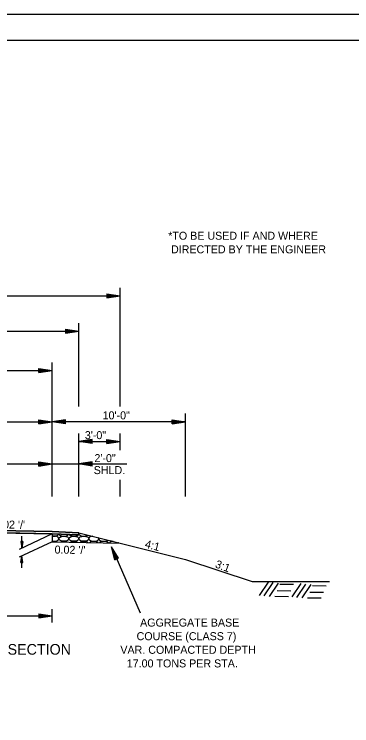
# Model space of a CAD drawing. Extents: x 1371763 to 1372860, y 385599 to 385872.
# Drawn here: x 1372776.6 to 1372801.9, y 385651.9 to 385705.3 of the extents above; entities that cross this region are included whole.
import ezdxf

# ---------------------------------------------------------------- set-up
doc = ezdxf.new("R2010")
doc.units = 0
for name, color, linetype in [('R_Border', 7, 'Continuous'), ('R_Draft', 7, 'Continuous'), ('R_Fin Surface', 7, 'Continuous'), ('R_No Plot', 7, 'Continuous')]:
    doc.layers.add(name, color=color, linetype=linetype)

msp = doc.modelspace()

# ---------------------------------------------------------------- linework, layer by layer
at = {"layer": 'R_Border'}
msp.add_line((1372699.208, 385703.307), (1372857.298, 385703.307), dxfattribs=at)
at = {"layer": 'R_Draft'}
for p, q in [((1372784.547, 385675.852), (1372784.547, 385684.754)), ((1372752.376, 385684.154), (1372784.547, 385684.154)), ((1372783.547, 385684.304), (1372784.547, 385684.154)), ((1372783.547, 385684.304), (1372783.547, 385684.004)), ((1372783.547, 385684.279), (1372784.38, 385684.154)), ((1372783.547, 385684.254), (1372784.208, 385684.154)), ((1372783.547, 385684.229), (1372784.042, 385684.154)), ((1372783.547, 385684.203), (1372783.872, 385684.154)), ((1372783.547, 385684.178), (1372783.705, 385684.154)), ((1372783.547, 385684.004), (1372784.547, 385684.154)), ((1372783.547, 385684.105), (1372783.872, 385684.154)), ((1372783.547, 385684.055), (1372784.208, 385684.154)), ((1372783.547, 385684.029), (1372784.38, 385684.154)), ((1372783.547, 385684.08), (1372784.042, 385684.154)), ((1372783.547, 385684.131), (1372783.705, 385684.154)), ((1372781.46, 385675.852), (1372781.46, 385682.102)), ((1372755.463, 385681.502), (1372781.46, 385681.502)), ((1372780.46, 385681.652), (1372781.46, 385681.502)), ((1372780.46, 385681.652), (1372780.46, 385681.352)), ((1372780.46, 385681.627), (1372781.293, 385681.502)), ((1372780.46, 385681.602), (1372781.121, 385681.502)), ((1372780.46, 385681.577), (1372780.955, 385681.502)), ((1372780.46, 385681.551), (1372780.785, 385681.502)), ((1372780.46, 385681.526), (1372780.618, 385681.502)), ((1372780.46, 385681.352), (1372781.46, 385681.502)), ((1372780.46, 385681.453), (1372780.785, 385681.502)), ((1372780.46, 385681.403), (1372781.121, 385681.502)), ((1372780.46, 385681.377), (1372781.293, 385681.502)), ((1372780.46, 385681.428), (1372780.955, 385681.502)), ((1372780.46, 385681.479), (1372780.618, 385681.502)), ((1372778.462, 385678.697), (1372779.462, 385678.547)), ((1372778.462, 385678.397), (1372778.462, 385678.697)), ((1372778.462, 385678.672), (1372779.295, 385678.547)), ((1372779.462, 385669.102), (1372779.462, 385679.147)), ((1372757.462, 385678.546), (1372779.462, 385678.547)), ((1372778.462, 385678.646), (1372779.123, 385678.547)), ((1372778.462, 385678.621), (1372778.956, 385678.547)), ((1372778.462, 385678.596), (1372778.787, 385678.547)), ((1372778.462, 385678.57), (1372778.62, 385678.547)), ((1372778.462, 385678.397), (1372779.462, 385678.547)), ((1372778.462, 385678.498), (1372778.787, 385678.547)), ((1372778.462, 385678.447), (1372779.123, 385678.547)), ((1372778.462, 385678.422), (1372779.295, 385678.547)), ((1372778.462, 385678.472), (1372778.956, 385678.547)), ((1372778.462, 385678.523), (1372778.62, 385678.547)), ((1372789.462, 385669.102), (1372789.462, 385675.327)), ((1372757.462, 385674.702), (1372779.462, 385674.702)), ((1372778.462, 385674.852), (1372779.462, 385674.702)), ((1372778.462, 385674.552), (1372778.462, 385674.852)), ((1372778.462, 385674.827), (1372779.295, 385674.702)), ((1372778.462, 385674.802), (1372779.123, 385674.702)), ((1372778.462, 385674.777), (1372778.956, 385674.702)), ((1372778.462, 385674.751), (1372778.787, 385674.702)), ((1372778.462, 385674.726), (1372778.62, 385674.702)), ((1372778.462, 385674.552), (1372779.462, 385674.702)), ((1372778.462, 385674.654), (1372778.787, 385674.702)), ((1372778.462, 385674.603), (1372779.123, 385674.702)), ((1372778.462, 385674.577), (1372779.295, 385674.702)), ((1372778.462, 385674.628), (1372778.956, 385674.702)), ((1372778.462, 385674.679), (1372778.62, 385674.702)), ((1372780.462, 385674.852), (1372779.462, 385674.702)), ((1372789.462, 385674.702), (1372779.462, 385674.702)), ((1372780.462, 385674.552), (1372779.462, 385674.702)), ((1372780.462, 385674.827), (1372779.629, 385674.702)), ((1372780.462, 385674.577), (1372779.629, 385674.702)), ((1372780.462, 385674.802), (1372779.801, 385674.702)), ((1372780.462, 385674.603), (1372779.801, 385674.702)), ((1372780.462, 385674.777), (1372779.967, 385674.702)), ((1372780.462, 385674.628), (1372779.967, 385674.702)), ((1372780.462, 385674.751), (1372780.137, 385674.702)), ((1372780.462, 385674.654), (1372780.137, 385674.702)), ((1372780.462, 385674.726), (1372780.304, 385674.702)), ((1372780.462, 385674.679), (1372780.304, 385674.702)), ((1372780.462, 385674.552), (1372780.462, 385674.852)), ((1372788.462, 385674.852), (1372789.462, 385674.702)), ((1372788.462, 385674.552), (1372788.462, 385674.852)), ((1372788.462, 385674.827), (1372789.295, 385674.702)), ((1372788.462, 385674.802), (1372789.123, 385674.702)), ((1372788.462, 385674.777), (1372788.956, 385674.702)), ((1372788.462, 385674.751), (1372788.787, 385674.702)), ((1372788.462, 385674.726), (1372788.62, 385674.702)), ((1372788.462, 385674.552), (1372789.462, 385674.702)), ((1372788.462, 385674.654), (1372788.787, 385674.702)), ((1372788.462, 385674.603), (1372789.123, 385674.702)), ((1372788.462, 385674.577), (1372789.295, 385674.702)), ((1372788.462, 385674.628), (1372788.956, 385674.702)), ((1372788.462, 385674.679), (1372788.62, 385674.702)), ((1372781.46, 385669.102), (1372781.46, 385673.818)), ((1372782.46, 385673.368), (1372781.46, 385673.218)), ((1372782.46, 385673.343), (1372781.627, 385673.218)), ((1372782.46, 385673.318), (1372781.799, 385673.218)), ((1372782.46, 385673.068), (1372782.46, 385673.368)), ((1372783.547, 385673.368), (1372784.547, 385673.218)), ((1372783.547, 385673.068), (1372783.547, 385673.368)), ((1372783.547, 385673.343), (1372784.38, 385673.218)), ((1372783.547, 385673.318), (1372784.208, 385673.218)), ((1372784.547, 385672.568), (1372784.547, 385673.818)), ((1372782.46, 385673.068), (1372781.46, 385673.218)), ((1372781.46, 385673.218), (1372784.547, 385673.218)), ((1372782.46, 385673.093), (1372781.627, 385673.218)), ((1372782.46, 385673.119), (1372781.799, 385673.218)), ((1372782.46, 385673.293), (1372781.966, 385673.218)), ((1372782.46, 385673.144), (1372781.966, 385673.218)), ((1372782.46, 385673.267), (1372782.135, 385673.218)), ((1372782.46, 385673.17), (1372782.135, 385673.218)), ((1372782.46, 385673.242), (1372782.302, 385673.218)), ((1372782.46, 385673.195), (1372782.302, 385673.218)), ((1372783.547, 385673.293), (1372784.042, 385673.218)), ((1372783.547, 385673.267), (1372783.872, 385673.218)), ((1372783.547, 385673.242), (1372783.705, 385673.218)), ((1372783.547, 385673.068), (1372784.547, 385673.218)), ((1372783.547, 385673.17), (1372783.872, 385673.218)), ((1372783.547, 385673.119), (1372784.208, 385673.218)), ((1372783.547, 385673.093), (1372784.38, 385673.218)), ((1372783.547, 385673.144), (1372784.042, 385673.218)), ((1372783.547, 385673.195), (1372783.705, 385673.218)), ((1372768.458, 385671.541), (1372785.058, 385671.541)), ((1372778.458, 385671.691), (1372779.458, 385671.541)), ((1372778.458, 385671.391), (1372778.458, 385671.691)), ((1372778.458, 385671.666), (1372779.291, 385671.541)), ((1372778.458, 385671.64), (1372779.119, 385671.541)), ((1372778.458, 385671.615), (1372778.953, 385671.541)), ((1372778.458, 385671.59), (1372778.783, 385671.541)), ((1372778.458, 385671.564), (1372778.616, 385671.541)), ((1372778.458, 385671.391), (1372779.458, 385671.541)), ((1372778.458, 385671.492), (1372778.783, 385671.541)), ((1372778.458, 385671.441), (1372779.119, 385671.541)), ((1372778.458, 385671.416), (1372779.291, 385671.541)), ((1372778.458, 385671.466), (1372778.953, 385671.541)), ((1372778.458, 385671.517), (1372778.616, 385671.541)), ((1372782.46, 385671.691), (1372781.46, 385671.541)), ((1372782.46, 385671.391), (1372781.46, 385671.541)), ((1372782.46, 385671.666), (1372781.627, 385671.541)), ((1372782.46, 385671.416), (1372781.627, 385671.541)), ((1372782.46, 385671.64), (1372781.799, 385671.541)), ((1372782.46, 385671.441), (1372781.799, 385671.541)), ((1372782.46, 385671.615), (1372781.966, 385671.541)), ((1372782.46, 385671.466), (1372781.966, 385671.541)), ((1372782.46, 385671.59), (1372782.135, 385671.541)), ((1372782.46, 385671.492), (1372782.135, 385671.541)), ((1372782.46, 385671.564), (1372782.302, 385671.541)), ((1372782.46, 385671.517), (1372782.302, 385671.541)), ((1372782.46, 385671.391), (1372782.46, 385671.691)), ((1372784.547, 385669.102), (1372784.547, 385670.352)), ((1372768.462, 385666.689), (1372779.462, 385666.469)), ((1372779.462, 385666.469), (1372768.462, 385666.689)), ((1372768.462, 385666.523), (1372779.462, 385666.303)), ((1372779.462, 385666.469), (1372781.46, 385666.389)), ((1372781.46, 385666.389), (1372779.462, 385666.469)), ((1372781.46, 385666.389), (1372789.46, 385664.389)), ((1372781.46, 385666.389), (1372781.46, 385666.223)), ((1372779.462, 385666.303), (1372776.974, 385665.131)), ((1372777.187, 385665.231), (1372777.187, 385666.131)), ((1372779.462, 385666.303), (1372779.462, 385665.719)), ((1372779.462, 385665.719), (1372776.974, 385664.547)), ((1372777.112, 385665.731), (1372777.187, 385665.231)), ((1372777.262, 385665.731), (1372777.112, 385665.731)), ((1372777.124, 385665.731), (1372777.187, 385665.314)), ((1372777.137, 385665.731), (1372777.187, 385665.4)), ((1372777.15, 385665.731), (1372777.187, 385665.484)), ((1372777.162, 385665.731), (1372777.187, 385665.568)), ((1372777.175, 385665.731), (1372777.187, 385665.652)), ((1372777.262, 385665.731), (1372777.187, 385665.231)), ((1372777.211, 385665.731), (1372777.187, 385665.568)), ((1372777.237, 385665.731), (1372777.187, 385665.4)), ((1372777.249, 385665.731), (1372777.187, 385665.314)), ((1372777.224, 385665.731), (1372777.187, 385665.484)), ((1372777.199, 385665.731), (1372777.187, 385665.652)), ((1372779.462, 385665.719), (1372784.547, 385665.618)), ((1372784.163, 385664.362), (1372783.898, 385665.338)), ((1372784.437, 385664.482), (1372783.898, 385665.338)), ((1372783.898, 385665.338), (1372786.069, 385660.393)), ((1372784.186, 385664.372), (1372783.965, 385665.185)), ((1372784.415, 385664.472), (1372783.965, 385665.185)), ((1372784.391, 385664.462), (1372784.034, 385665.027)), ((1372784.209, 385664.382), (1372784.034, 385665.027)), ((1372784.232, 385664.392), (1372784.101, 385664.875)), ((1372784.368, 385664.452), (1372784.101, 385664.875)), ((1372777.112, 385664.148), (1372777.187, 385664.648)), ((1372777.124, 385664.148), (1372777.187, 385664.564)), ((1372777.137, 385664.148), (1372777.187, 385664.478)), ((1372777.15, 385664.148), (1372777.187, 385664.395)), ((1372777.163, 385664.148), (1372777.187, 385664.31)), ((1372777.262, 385664.148), (1372777.187, 385664.648)), ((1372777.187, 385663.748), (1372777.187, 385664.648)), ((1372777.249, 385664.148), (1372777.187, 385664.564)), ((1372777.237, 385664.148), (1372777.187, 385664.478)), ((1372777.224, 385664.148), (1372777.187, 385664.395)), ((1372777.211, 385664.148), (1372777.187, 385664.31)), ((1372784.163, 385664.362), (1372784.437, 385664.482)), ((1372784.345, 385664.442), (1372784.169, 385664.72)), ((1372784.256, 385664.403), (1372784.169, 385664.72)), ((1372784.322, 385664.432), (1372784.237, 385664.567)), ((1372784.279, 385664.413), (1372784.237, 385664.567)), ((1372789.46, 385664.389), (1372794.46, 385662.723)), ((1372777.112, 385664.148), (1372777.262, 385664.148)), ((1372777.175, 385664.148), (1372777.187, 385664.227)), ((1372777.199, 385664.148), (1372777.187, 385664.227)), ((1372795.013, 385661.692), (1372795.689, 385662.693)), ((1372795.372, 385661.65), (1372796.048, 385662.651)), ((1372795.773, 385661.608), (1372796.449, 385662.61)), ((1372796.549, 385662.535), (1372797.566, 385662.526)), ((1372797.466, 385661.583), (1372798.142, 385662.585)), ((1372797.825, 385661.541), (1372798.501, 385662.543)), ((1372798.226, 385661.5), (1372798.901, 385662.501)), ((1372799.001, 385662.426), (1372800.019, 385662.418)), ((1372796.173, 385661.625), (1372797.191, 385661.617)), ((1372796.348, 385662.051), (1372797.366, 385662.042)), ((1372798.801, 385661.942), (1372799.819, 385661.934)), ((1372798.626, 385661.516), (1372799.644, 385661.508)), ((1372779.462, 385659.663), (1372779.462, 385660.663)), ((1372757.462, 385660.163), (1372779.462, 385660.163)), ((1372778.462, 385660.313), (1372779.462, 385660.163)), ((1372778.462, 385660.313), (1372778.462, 385660.013)), ((1372778.462, 385660.288), (1372779.295, 385660.163)), ((1372778.462, 385660.263), (1372779.123, 385660.163)), ((1372778.462, 385660.238), (1372778.956, 385660.163)), ((1372778.462, 385660.212), (1372778.787, 385660.163)), ((1372778.462, 385660.187), (1372778.62, 385660.163)), ((1372778.462, 385660.013), (1372779.462, 385660.163)), ((1372778.462, 385660.114), (1372778.787, 385660.163)), ((1372778.462, 385660.064), (1372779.123, 385660.163)), ((1372778.462, 385660.038), (1372779.295, 385660.163)), ((1372778.462, 385660.089), (1372778.956, 385660.163)), ((1372778.462, 385660.14), (1372778.62, 385660.163))]:
    msp.add_line(p, q, dxfattribs=at)
for points in [[(1372752.376, 385665.618), (1372757.462, 385665.719), (1372757.462, 385666.303), (1372768.462, 385666.523), (1372779.462, 385666.303), (1372779.462, 385665.719), (1372784.547, 385665.618)], [(1372768.462, 385666.523), (1372779.462, 385666.303), (1372781.46, 385666.223), (1372781.46, 385666.389)]]:
    msp.add_lwpolyline(points, dxfattribs=at)
msp.add_lwpolyline([(1372755.463, 385666.39), (1372757.462, 385666.469), (1372768.462, 385666.689), (1372779.462, 385666.469), (1372781.46, 385666.389), (1372781.46, 385666.223), (1372779.462, 385666.303), (1372768.462, 385666.523), (1372757.462, 385666.303), (1372755.463, 385666.223)], close=True, dxfattribs=at)
for centre, start_param, end_param in [((1372781.833, 385666.327), 2.83572, 3.029425), ((1372779.582, 385666.327), 4.385677, 6.055207), ((1372779.582, 385665.939), 4.385733, 8.180691), ((1372780.333, 385666.327), 3.373751, 5.89689), ((1372781.083, 385666.327), 3.540614, 5.730026), ((1372781.833, 385666.327), 3.25376, 5.689587), ((1372782.583, 385665.939), 1.783811, 6.741496), ((1372783.334, 385665.939), 2.773098, 5.752209), ((1372779.582, 385665.55), 0.993669, 1.89745), ((1372780.333, 385665.55), 0.858123, 2.206271), ((1372781.083, 385665.55), 0.742565, 2.32183), ((1372781.833, 385665.55), 0.639004, 2.425391), ((1372782.583, 385665.55), 0.543464, 2.520931), ((1372783.334, 385665.55), 0.453605, 2.61079), ((1372784.084, 385665.55), 1.674886, 2.696501), ((1372784.084, 385665.939), 3.947038, 4.578269), ((1372784.084, 385665.55), 0.367893, 0.567236), ((1372784.834, 385665.55), 2.710794, 2.779152)]:
    msp.add_ellipse(centre, major_axis=(0.375, 0), ratio=0.517889, start_param=start_param, end_param=end_param, dxfattribs=at)
for centre in [(1372780.333, 385665.939), (1372781.083, 385665.939), (1372781.833, 385665.939)]:
    msp.add_ellipse(centre, major_axis=(0.375, 0), ratio=0.517889, dxfattribs=at)
at = {"layer": 'R_Fin Surface'}
msp.add_line((1372794.46, 385662.723), (1372800.278, 385662.723), dxfattribs=at)
at = {"layer": 'R_No Plot'}
msp.add_line((1372693.007, 385705.254), (1372859.674, 385705.254), dxfattribs=at)
for points in [[(1372693.004, 385705.254), (1372859.674, 385705.254), (1372859.674, 385598.585), (1372693.004, 385598.585)], [(1372816.168, 385703.307), (1372825.978, 385703.307), (1372825.978, 385698.367), (1372834.034, 385698.367), (1372845.634, 385698.367), (1372845.634, 385682.032), (1372857.238, 385682.032), (1372857.298, 385600.577), (1372699.208, 385600.577), (1372699.208, 385703.307)]]:
    msp.add_lwpolyline(points, close=True, dxfattribs=at)

# ---------------------------------------------------------------- texts
at = {"layer": 'R_Draft'}
for s, rotation, p in [('*TO BE USED IF AND WHERE ', 360, (1372788.163, 385688.352)), ('DIRECTED BY THE ENGINEER', 360, (1372788.374, 385687.332)), ('10\'-0"', 0, (1372783.241, 385674.888)), ('3\'-0"', 360, (1372781.905, 385673.405)), ('2\'-0"', 360, (1372782.626, 385671.683)), ('SHLD.', 360, (1372782.572, 385670.783)), ("0.02 '/'", 359.0147, (1372775.094, 385666.722)), ("0.02 '/'", 359.0147, (1372779.631, 385664.83)), ('4:1', 345.9638, (1372786.373, 385665.279)), ('3:1', 339.4451, (1372791.638, 385663.805)), ('AGGREGATE BASE ', 360, (1372786.055, 385659.354)), ('COURSE (CLASS 7)', 360, (1372785.79, 385658.334)), ('VAR. COMPACTED DEPTH', 360, (1372784.571, 385657.314)), ('17.00 TONS PER STA.', 360, (1372785.053, 385656.294))]:
    msp.add_text(s, height=0.6, rotation=rotation, dxfattribs=at).set_placement(p)
msp.add_text('E. PLENTYWOOD RD. - NOTCH AND WIDEN SECTION', height=0.8, dxfattribs=at).set_placement((1372753.586, 385657.248))

doc.saveas('drawing.dxf')
